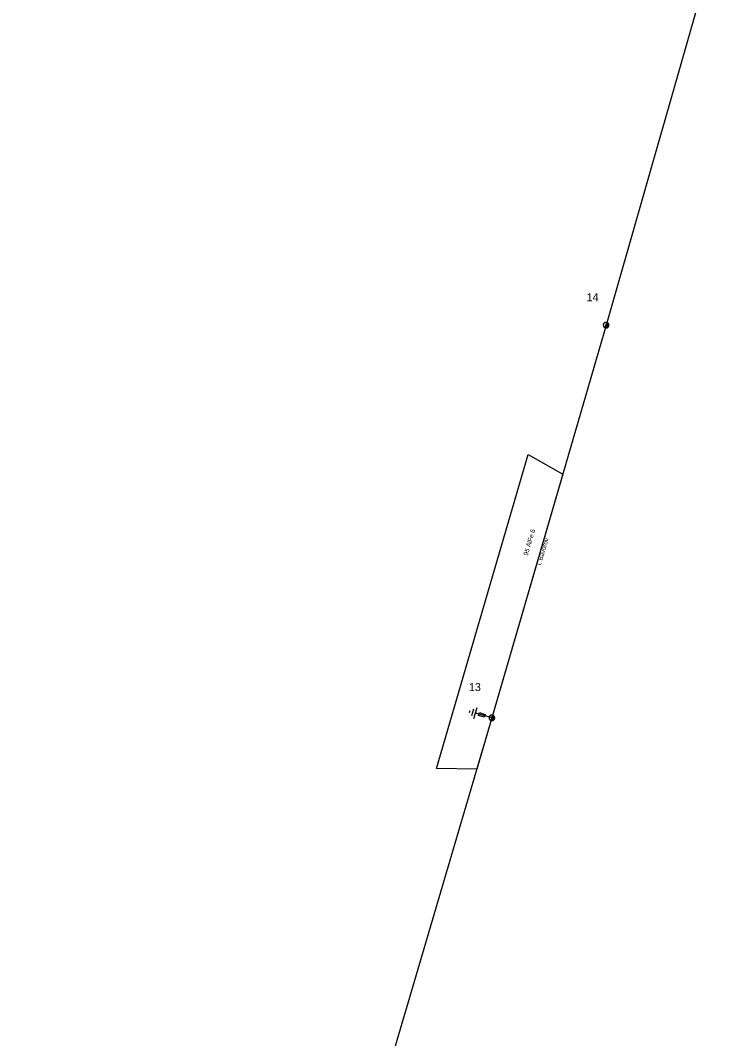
# Model space of a CAD drawing. Extents: x -788491 to -785797, y -1154753 to -1152002.
# Drawn here: x -786846.7 to -786694.3, y -1153064.5 to -1152841.8 of the extents above; entities that cross this region are included whole.
import ezdxf

# ---------------------------------------------------------------- set-up
doc = ezdxf.new("R2010")
doc.units = 0
for name, color, linetype in [('Vrstva 1', 7, 'Continuous'), ('Vrstva 13', 7, 'Continuous'), ('Vrstva 14', 7, 'Continuous'), ('Vrstva 15', 7, 'Continuous'), ('Vrstva 16', 7, 'Continuous'), ('Vrstva 2', 7, 'Continuous'), ('Vrstva 3', 7, 'Continuous'), ('Vrstva 35', 7, 'Continuous')]:
    doc.layers.add(name, color=color, linetype=linetype)

# ---------------------------------------------------------------- blocks, each defined once
blk = doc.blocks.new('VN440')
at = {"layer": 'Vrstva 2'}
for points in [[(1.22, 0), (1.21, 0.13), (1.19, 0.25), (1.16, 0.38), (1.11, 0.5), (1.05, 0.61), (0.98, 0.72), (0.9, 0.82), (0.81, 0.91), (0.71, 0.99), (0.6, 1.06), (0.49, 1.12), (0.37, 1.16), (0.25, 1.2), (0.12, 1.22), (-0.01, 1.22), (-0.14, 1.22), (-0.26, 1.2), (-0.39, 1.16), (-0.51, 1.12), (-0.62, 1.06), (-0.73, 0.99), (-0.83, 0.91), (-0.92, 0.82), (-1, 0.72), (-1.07, 0.61), (-1.13, 0.5), (-1.18, 0.38), (-1.21, 0.25), (-1.23, 0.13), (-1.24, 0), (-1.23, -0.13), (-1.21, -0.26), (-1.18, -0.38), (-1.13, -0.5), (-1.07, -0.62), (-1, -0.73), (-0.92, -0.83), (-0.83, -0.92), (-0.73, -1), (-0.62, -1.07), (-0.51, -1.13), (-0.39, -1.17), (-0.26, -1.2), (-0.14, -1.23), (-0.01, -1.23), (0.12, -1.23), (0.25, -1.2), (0.37, -1.17), (0.49, -1.13), (0.6, -1.07), (0.71, -1), (0.81, -0.92), (0.9, -0.83), (0.98, -0.73), (1.05, -0.62), (1.11, -0.5), (1.16, -0.38), (1.19, -0.26), (1.21, -0.13), (1.22, 0)], [(-1.24, 0), (1.22, 0)], [(-1.18, -0.34), (1.1, -0.34)], [(-1.01, -0.63), (0.97, -0.63)], [(-0.74, -0.92), (0.68, -0.92)]]:
    blk.add_lwpolyline(points, dxfattribs=at)
blk = doc.blocks.new('VN820')
at = {"layer": 'Vrstva 13'}
for points in [[(0, 0), (0, -2.1)], [(-0.32, -1.63), (0.34, -1.63)], [(-0.32, -2.95), (-0.32, -1.63)], [(0, -2.1), (-0.12, -1.86)], [(0, -2.1), (0.12, -1.86)], [(0.34, -1.63), (0.34, -2.95)], [(0.34, -2.95), (-0.32, -2.95)], [(0, -2.95), (0, -3.75)]]:
    blk.add_lwpolyline(points, dxfattribs=at)
blk = doc.blocks.new('VN810')
at = {"layer": 'Vrstva 14'}
for points in [[(0, -1.25), (0, -3.75)], [(1.25, -3.75), (-1.25, -3.75)], [(0.77, -4.37), (-0.8, -4.37)], [(0, -5), (-0.25, -5)], [(0.27, -5), (0, -5)]]:
    blk.add_lwpolyline(points, dxfattribs=at)

msp = doc.modelspace()

# ---------------------------------------------------------------- linework, layer by layer
at = {"layer": 'Vrstva 1'}
msp.add_lwpolyline([(-786697.17, -1152540.35), (-786697.15, -1152542.67), (-786696.15, -1152676.82), (-786694.35, -1152824), (-786718.54, -1152908.44), (-786743.54, -1152994.34), (-786773.89, -1153097.37), (-786798.2, -1153180.7), (-786846.74, -1153228.64)], dxfattribs=at)
at = {"layer": 'Vrstva 35'}
msp.add_lwpolyline([(-786728.03, -1152941.03), (-786743.54, -1152994.34), (-786746.85, -1153005.57), (-786755.67, -1153005.43), (-786751.7, -1152991.95), (-786735.63, -1152936.74)], close=True, dxfattribs=at)

# ---------------------------------------------------------------- block references
at = {"layer": 'Vrstva 13'}
for p, xscale, yscale, rotation in [((-786718.54, -1152908.44), 0.5, 0.5, 73.73811668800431), ((-786743.54, -1152994.34), 0.49999999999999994, 0.5000000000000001, 74.11692489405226)]:
    msp.add_blockref('VN440', p, dxfattribs=dict(at, xscale=xscale, yscale=yscale, rotation=rotation))
at = {"layer": 'Vrstva 15', "rotation": -106.22690217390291}
msp.add_blockref('VN810', (-786743.54, -1152994.34), dxfattribs=at)
at = {"layer": 'Vrstva 16', "rotation": -106.22690217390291}
msp.add_blockref('VN820', (-786743.54, -1152994.34), dxfattribs=at)

# ---------------------------------------------------------------- texts
at = {"layer": 'Vrstva 14'}
for s, p in [('14', (-786722.8, -1152903.21)), ('13', (-786748.55, -1152988.48))]:
    msp.add_text(s, height=1.75, dxfattribs=at).set_placement(p)
at = {"layer": 'Vrstva 2'}
msp.add_text('95 AlFe 6', height=1, rotation=73.773, dxfattribs=at).set_placement((-786735.69, -1152958.91))
at = {"layer": 'Vrstva 3'}
msp.add_text('l. Bavorov', height=1, rotation=73.773, dxfattribs=at).set_placement((-786732.81, -1152961.04))

doc.saveas('drawing.dxf')
